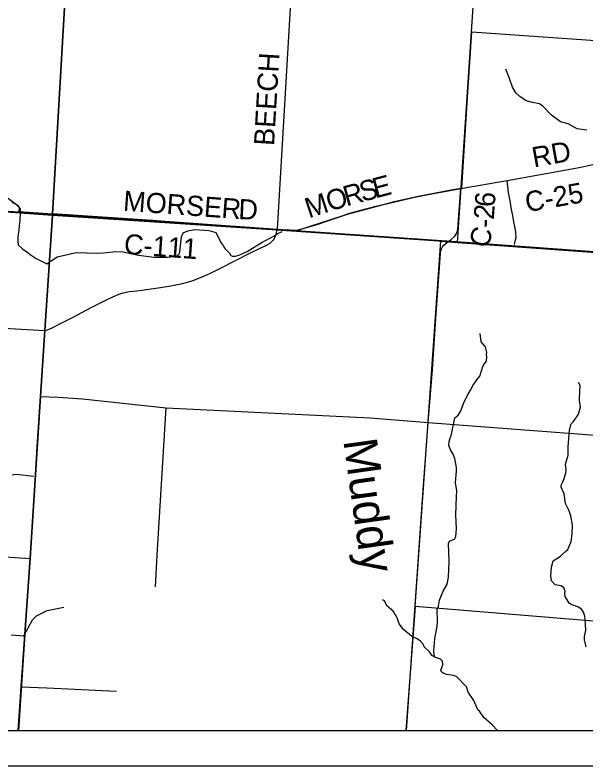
# Model space of a CAD drawing. Extents: x 0 to 91.3, y -0.7 to 22.
# Drawn here: x 4.519 to 6.125, y 14 to 16.113 of the extents above; entities that cross this region are included whole.
import ezdxf

# ---------------------------------------------------------------- set-up
doc = ezdxf.new("R2010")
doc.units = 0
for name, color, linetype in [('GM_X_City_Street', 7, 'Continuous'), ('GM_X_Corporation', 7, 'Continuous'), ('GM_X_County_Road', 7, 'Continuous'), ('GM_X_County_Road_Text', 7, 'Continuous'), ('GM_X_Minor_River', 7, 'Continuous'), ('GM_X_Minor_River_Text', 7, 'Continuous'), ('GM_X_Township_Road', 7, 'Continuous'), ('GM_X_Township_Road_Text', 7, 'Continuous'), ('SH_Data', 7, 'Continuous')]:
    doc.layers.add(name, color=color, linetype=linetype)

msp = doc.modelspace()

# ---------------------------------------------------------------- linework, layer by layer
at = {"layer": 'GM_X_City_Street'}
for p, q in [((4.919, 14.593), (4.9438, 15.0077)), ((5.6815, 14.9665), (6.3908, 14.9126)), ((4.9137, 14.5041), (4.919, 14.593))]:
    msp.add_line(p, q, dxfattribs=at)
for points in [[(4.6242, 15.5533), (4.9057, 15.534), (4.9418, 15.531), (5.067, 15.5218), (5.1639, 15.5152), (5.2022, 15.5131), (5.2558, 15.51)], [(4.5903, 15.0398), (4.6402, 15.038), (4.709, 15.033), (4.9438, 15.0077), (5.5178, 14.9797), (5.6815, 14.9665)], [(4.5363, 14.2229), (4.6078, 14.2201), (4.8041, 14.2108)]]:
    msp.add_lwpolyline(points, dxfattribs=at)
at = {"layer": 'GM_X_Corporation'}
for points in [[(4.8242, 18.6326), (4.7833, 18.1361), (4.7799, 18.0944), (4.7688, 17.9561), (4.7562, 17.8002), (4.7391, 17.5254), (4.7381, 17.5094), (4.7369, 17.4842), (4.7039, 16.921), (4.6966, 16.7952), (4.624, 15.5538), (4.6241, 15.5494), (4.6027, 15.2253), (4.5901, 15.0403), (4.5616, 14.5843), (4.5361, 14.2234), (4.5273, 14.1), (8.9, 14.1), (8.9, 20.9)], [(2.1, 20.8844), (2.1, 14.1), (4.5273, 14.1), (4.5361, 14.2234), (4.5616, 14.5843), (4.5901, 15.0403), (4.6027, 15.2253), (4.6241, 15.5494), (4.624, 15.5538), (4.6966, 16.7952), (4.7039, 16.921), (4.7369, 17.4842), (4.7381, 17.5094), (4.7391, 17.5254), (4.7562, 17.8002), (4.7688, 17.9561), (4.7799, 18.0944), (4.7833, 18.1361), (4.8242, 18.6326)], [(2.1, 20.8844), (2.1, 15.7138), (2.3611, 15.6969), (2.7426, 15.6727), (3.1007, 15.6507), (3.7652, 15.6088), (4.1118, 15.5861), (4.6241, 15.5494), (4.624, 15.5538), (4.6966, 16.7952), (4.7039, 16.921), (4.7369, 17.4842), (4.7381, 17.5094), (4.7391, 17.5254), (4.7562, 17.8002), (4.7688, 17.9561), (4.7799, 18.0944), (4.7833, 18.1361), (4.8242, 18.6326)], [(4.8242, 18.6326), (4.7833, 18.1361), (4.7799, 18.0944), (4.7688, 17.9561), (4.7562, 17.8002), (4.7391, 17.5254), (4.7381, 17.5094), (4.7369, 17.4842), (4.7039, 16.921), (4.6966, 16.7952), (4.624, 15.5538), (4.6241, 15.5494), (5.2553, 15.5081), (5.7371, 15.476), (6.438, 15.425), (7.1732, 15.3725), (7.6407, 15.3389), (8.8181, 15.2648), (8.9, 15.2596), (8.9, 20.4953)], [(4.4708, 15.6178), (4.5262, 15.577), (4.5303, 15.5712), (4.5296, 15.5598), (4.624, 15.5538), (4.6272, 15.5536), (4.7307, 15.5465), (4.9009, 15.5349), (4.9055, 15.5345), (4.9136, 15.534), (4.9275, 15.5328), (4.9415, 15.5315), (5.0202, 15.5256), (5.1746, 15.5156), (5.2557, 15.5097), (5.2873, 15.5075), (5.3098, 15.5058), (5.3464, 15.5178), (5.3806, 15.5289), (5.4074, 15.5377), (5.4473, 15.5511), (5.454, 15.5532), (5.4878, 15.5629), (5.5347, 15.575), (5.5619, 15.582), (5.5816, 15.5868), (5.6525, 15.6034), (5.7461, 15.6206), (5.7733, 15.6254), (5.7761, 15.6259), (5.7902, 15.8519), (5.8036, 16.0651), (6.313, 16.0296)]]:
    msp.add_lwpolyline(points, dxfattribs=at)
for points in [[(5.8298, 16.4755), (6.8465, 16.3992), (6.7835, 15.4003), (6.727, 15.4038), (5.7634, 15.4732)], [(2.1, 15.7138), (2.1, 14.1), (4.5273, 14.1), (4.5361, 14.2234), (4.5616, 14.5843), (4.5901, 15.0403), (4.6027, 15.2253), (4.6241, 15.5494), (4.1118, 15.5861), (3.7652, 15.6088), (3.1007, 15.6507), (2.7426, 15.6727), (2.3611, 15.6969)], [(4.5286, 14.1), (8.9, 14.1), (8.9, 15.2593), (7.6407, 15.3389), (7.1732, 15.3725), (5.7332, 15.4763), (5.3098, 15.5058), (4.9415, 15.5315), (4.9055, 15.5345), (4.624, 15.5538)], [(4.5273, 14.1), (8.9, 14.1), (8.9, 15.2596), (8.8181, 15.2648), (7.6407, 15.3389), (7.1732, 15.3725), (6.438, 15.425), (5.7371, 15.476), (5.2553, 15.5081), (4.6241, 15.5494), (4.6027, 15.2253), (4.5901, 15.0403), (4.5616, 14.5843), (4.5361, 14.2234)], [(5.7168, 15.4767), (5.7634, 15.4732), (6.727, 15.4038), (6.6586, 14.3652), (5.6446, 14.4487)], [(5.6181, 14.1), (6.6403, 14.1), (6.6586, 14.3652), (5.6446, 14.4487)]]:
    msp.add_lwpolyline(points, close=True, dxfattribs=at)
at = {"layer": 'GM_X_County_Road'}
for p, q in [((5.7729, 15.6244), (5.9032, 15.6474)), ((4.112, 15.5855), (4.5298, 15.5592)), ((4.5298, 15.5592), (4.6242, 15.5533))]:
    msp.add_line(p, q, dxfattribs=at)
for points in [[(5.9032, 15.6474), (6.0541, 15.6743), (6.1102, 15.6849), (6.1444, 15.6918), (6.1946, 15.7021), (6.2285, 15.7083), (6.2474, 15.7112), (6.2642, 15.7133), (6.2926, 15.7156)], [(5.306, 15.5079), (5.3158, 15.5087), (5.3257, 15.5109), (5.3359, 15.5138), (5.3686, 15.5237), (5.4199, 15.5412), (5.454, 15.5524), (5.5104, 15.568), (5.5553, 15.5798), (5.6473, 15.6015), (5.6958, 15.6106), (5.7729, 15.6244)], [(5.7462, 15.4816), (5.7565, 15.491), (5.7599, 15.4962), (5.7631, 15.5026), (5.7641, 15.5092), (5.7653, 15.5208), (5.7666, 15.537), (5.7729, 15.6244)], [(4.603, 15.2248), (4.6099, 15.2269), (4.6231, 15.2328), (4.649, 15.246), (4.6822, 15.2632), (4.733, 15.2896), (4.7796, 15.3131), (4.8024, 15.3241), (4.8132, 15.3283), (4.8194, 15.33), (4.8251, 15.3316), (4.8317, 15.333), (4.8412, 15.3346), (4.8614, 15.3372), (4.8754, 15.3391), (4.902, 15.3429), (4.9283, 15.3465), (4.9519, 15.3502), (4.9716, 15.3538), (4.9899, 15.3577), (5.0044, 15.3612), (5.0221, 15.3668), (5.0342, 15.3711), (5.0472, 15.3768), (5.0584, 15.3817), (5.0702, 15.3876), (5.0946, 15.3999), (5.1808, 15.4434), (5.2266, 15.4652), (5.2366, 15.4711), (5.2426, 15.4765), (5.2474, 15.4825), (5.2519, 15.4912), (5.2541, 15.4978), (5.2555, 15.5076), (5.2558, 15.51)], [(5.2558, 15.51), (5.2815, 15.5085), (5.2926, 15.508), (5.3031, 15.5076), (5.306, 15.5079)], [(5.6203, 14.1), (5.6663, 14.7627), (5.6719, 14.8391), (5.6815, 14.9665), (5.6928, 15.1159), (5.7031, 15.2735), (5.7113, 15.3767), (5.7157, 15.4419), (5.7169, 15.4492), (5.7184, 15.4554), (5.7216, 15.461), (5.7255, 15.4657), (5.7373, 15.4755), (5.7447, 15.4802), (5.7462, 15.4816)], [(4.0898, 15.2565), (4.1044, 15.2553), (4.2363, 15.2464), (4.3377, 15.2405), (4.603, 15.2248)]]:
    msp.add_lwpolyline(points, dxfattribs=at)
at = {"layer": 'GM_X_Minor_River'}
for points in [[(6.1279, 15.7884), (6.0998, 15.7923), (6.0753, 15.8069), (6.0537, 15.8119), (6.0277, 15.8311), (6.0032, 15.8566), (5.9941, 15.8627), (5.9744, 15.867), (5.9566, 15.8713), (5.9389, 15.8832), (5.9279, 15.8942), (5.9185, 15.9098), (5.9103, 15.9345), (5.8991, 15.9604)], [(4.5101, 15.5865), (4.5233, 15.5796), (4.5328, 15.5678), (4.5338, 15.5564), (4.5326, 15.5431), (4.5318, 15.5336), (4.5302, 15.5211), (4.529, 15.5078), (4.5274, 15.4965), (4.5266, 15.4866), (4.5265, 15.4767), (4.5276, 15.4661), (4.54, 15.455), (4.5517, 15.4462), (4.5638, 15.437), (4.5778, 15.4278), (4.6085, 15.4127)], [(4.6085, 15.4127), (4.6373, 15.4327), (4.6905, 15.4445), (4.7512, 15.4431), (4.7676, 15.4434), (4.8025, 15.4474), (4.823, 15.4469), (4.8658, 15.4372), (4.9098, 15.4313), (4.9477, 15.4315), (4.9735, 15.4344), (4.9812, 15.442), (4.9823, 15.4469), (4.9867, 15.489), (4.9921, 15.5004), (5.005, 15.506), (5.0248, 15.5093), (5.0639, 15.5068), (5.0714, 15.5045), (5.0839, 15.501), (5.0993, 15.4702), (5.1046, 15.4645), (5.1091, 15.4557), (5.122, 15.4428), (5.1261, 15.4363), (5.131, 15.434), (5.1394, 15.4347), (5.1512, 15.4381), (5.1717, 15.4471), (5.2136, 15.4742), (5.2471, 15.4911), (5.2577, 15.4979), (5.2707, 15.5035)], [(5.6987, 14.3068), (5.6973, 14.3236), (5.6998, 14.3581), (5.7064, 14.3929), (5.7077, 14.4066), (5.706, 14.4403), (5.7102, 14.4494), (5.7133, 14.4668), (5.7229, 14.4922), (5.734, 14.5092), (5.7356, 14.516), (5.7379, 14.5311), (5.7401, 14.5759), (5.7385, 14.6259), (5.7411, 14.6323), (5.748, 14.635), (5.7556, 14.6379), (5.759, 14.6455), (5.7611, 14.6671), (5.7586, 14.7065), (5.7612, 14.7585), (5.7613, 14.7751), (5.7598, 14.785), (5.7584, 14.7972), (5.7605, 14.8294), (5.7605, 14.84), (5.7565, 14.8647), (5.7512, 14.8772), (5.7449, 14.8875), (5.7396, 14.9015), (5.7404, 14.9129), (5.7428, 14.9235), (5.7458, 14.9292), (5.7564, 14.9795), (5.7651, 14.9867), (5.7716, 14.9976), (5.7828, 15.0249), (5.7935, 15.0457), (5.8, 15.0574), (5.8073, 15.0714), (5.8176, 15.0865), (5.8268, 15.0963), (5.836, 15.1269), (5.8448, 15.1386), (5.8457, 15.1508), (5.8449, 15.158), (5.8457, 15.164), (5.8428, 15.1796), (5.8304, 15.1937), (5.8278, 15.2172)], [(6.1258, 14.3351), (6.121, 14.3545), (6.121, 14.3639), (6.1249, 14.3817), (6.1224, 14.414), (6.1214, 14.4219), (6.1184, 14.4329), (6.112, 14.4409), (6.1018, 14.4478), (6.0832, 14.4544), (6.078, 14.4582), (6.0663, 14.4772), (6.0652, 14.4856), (6.0668, 14.4916), (6.063, 14.5008), (6.0551, 14.5069), (6.0381, 14.5092), (6.0283, 14.5211), (6.0257, 14.534), (6.0277, 14.559), (6.0331, 14.5771), (6.0529, 14.5899), (6.059, 14.5956), (6.0674, 14.6031), (6.0739, 14.6091), (6.0835, 14.6314), (6.0863, 14.6523), (6.0871, 14.6777), (6.082, 14.7035), (6.0775, 14.7179), (6.0674, 14.7381), (6.0634, 14.7654), (6.0555, 14.7848), (6.0556, 14.7897), (6.0598, 14.7995), (6.064, 14.8086), (6.0683, 14.8245), (6.0691, 14.8336), (6.0673, 14.8488), (6.0746, 14.8741), (6.0747, 14.8992), (6.0776, 14.9314), (6.0788, 14.9461), (6.0834, 14.9628), (6.0903, 14.9688), (6.1037, 14.99), (6.1095, 15.01), (6.1069, 15.0279), (6.107, 15.0339), (6.1083, 15.0707), (6.1042, 15.0787)], [(4.511, 14.8195), (4.5224, 14.8213), (4.5713, 14.8153)], [(5.7231, 14.2609), (5.7182, 14.2647), (5.7164, 14.27), (5.7225, 14.2844), (5.7218, 14.295), (5.7162, 14.3007), (5.7014, 14.3054), (5.6931, 14.3096), (5.689, 14.3157), (5.6848, 14.3214), (5.6701, 14.3351), (5.6667, 14.3427), (5.6596, 14.3511), (5.6501, 14.3576), (5.6339, 14.3649), (5.6124, 14.3833), (5.5996, 14.4004), (5.5936, 14.4167), (5.5914, 14.4224), (5.5827, 14.4358), (5.565, 14.4506), (5.5579, 14.4643), (5.5526, 14.4674)], [(4.5434, 14.3663), (4.5677, 14.4111), (4.5792, 14.4225), (4.6092, 14.4371), (4.6556, 14.4464)], [(4.5082, 14.3691), (4.5434, 14.3663)], [(5.8758, 14.1), (5.8607, 14.116), (5.8381, 14.1362), (5.8257, 14.1538), (5.8208, 14.1576), (5.8099, 14.1842), (5.7934, 14.2078), (5.7893, 14.2226), (5.7618, 14.2508), (5.7534, 14.2543), (5.7334, 14.257), (5.7231, 14.2609)]]:
    msp.add_lwpolyline(points, dxfattribs=at)
at = {"layer": 'GM_X_Township_Road'}
for points in [[(5.3281, 16.6864), (5.328, 16.6844), (5.3244, 16.6266), (5.3225, 16.5967), (5.3088, 16.3806), (5.3019, 16.2634), (5.3016, 16.2584), (5.2917, 16.1165), (5.2558, 15.51)], [(5.9241, 15.4676), (5.9271, 15.4805), (5.9282, 15.4866), (5.9273, 15.4999), (5.9265, 15.5082), (5.9245, 15.5177), (5.9221, 15.5314), (5.9193, 15.5488), (5.9157, 15.5659), (5.9117, 15.5905), (5.9074, 15.6137), (5.9032, 15.6474)], [(4.5814, 14.898), (4.5903, 15.0398), (4.603, 15.2248)], [(4.5617, 14.5808), (4.5619, 14.5838), (4.5814, 14.898)], [(3.5357, 14.6514), (3.9905, 14.6197), (4.2607, 14.6038), (4.5619, 14.5838)], [(4.5276, 14.1), (4.5363, 14.2229), (4.5609, 14.5709), (4.5617, 14.5808)]]:
    msp.add_lwpolyline(points, dxfattribs=at)
at = {"layer": 'SH_Data'}
for p, q in [((2.1, 14.1), (8.9, 14.1)), ((2, 14), (9, 14))]:
    msp.add_line(p, q, dxfattribs=at)

# ---------------------------------------------------------------- texts
at = {"layer": 'GM_X_County_Road_Text'}
for s, height, rotation, p in [('RD', 0.05682, 10.259, (5.9785, 15.6837)), ('E', 0.0568, 14.8699, (5.5328, 15.5966)), ('R', 0.0568, 15.6012, (5.451, 15.5742)), ('S', 0.0568, 14.8775, (5.4957, 15.5867)), ('C-25', 0.05682, 10.036, (5.959, 15.5577)), ('MORSE', 0.05682, 355.8298, (4.8215, 15.5623)), ('O', 0.0568, 17.2299, (5.4036, 15.5596)), ('R', 0.0568, 355.8632, (5.0981, 15.5423)), ('D', 0.0568, 357.372, (5.1462, 15.5388)), ('M', 0.0568, 18.1351, (5.3453, 15.5404)), ('6', 0.0568, 85.8927, (5.8682, 15.5712)), ('2', 0.0568, 85.7182, (5.8655, 15.5361)), ('-', 0.0568, 87.0887, (5.8644, 15.5132)), ('C', 0.0568, 73.8267, (5.849, 15.4542)), ('C-111', 0.05682, 355.8747, (4.8238, 15.4408))]:
    msp.add_text(s, height=height, rotation=rotation, dxfattribs=at).set_placement(p)
at = {"layer": 'GM_X_Minor_River_Text'}
msp.add_text('Muddy', height=0.09469, rotation=278.0011, dxfattribs=at).set_placement((5.442, 14.9156))
at = {"layer": 'GM_X_Township_Road_Text'}
msp.add_text('BEECH', height=0.05682, rotation=86.6453, dxfattribs=at).set_placement((5.2474, 15.7438))

doc.saveas('drawing.dxf')
